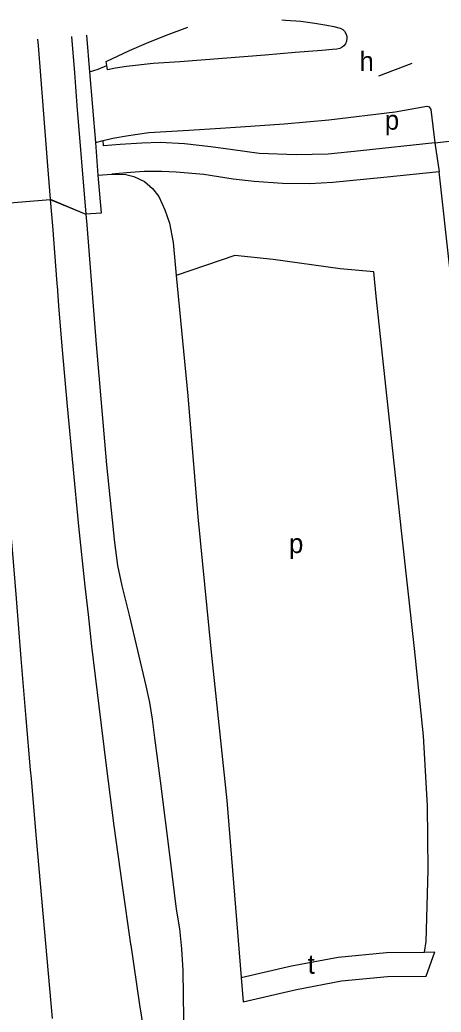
# Model space of a CAD drawing. Extents: x 157646 to 159241, y 379213 to 381217.
# Drawn here: x 157938.7 to 158026.1, y 380686.9 to 380892.6 of the extents above; entities that cross this region are included whole.
import ezdxf

# ---------------------------------------------------------------- set-up
doc = ezdxf.new("R2010")
doc.units = 0
for name, color, linetype in [('BLT_Basislijn', 7, 'Continuous'), ('BLT_Centroide', 7, 'Continuous'), ('BLT_Vlakafsluiter', 7, 'Continuous')]:
    doc.layers.add(name, color=color, linetype=linetype)

msp = doc.modelspace()

# ---------------------------------------------------------------- linework, layer by layer
at = {"layer": 'BLT_Basislijn'}
for p, q in [((157952.53, 380889.43), (157953.11, 380881.88)), ((157953.11, 380881.88), (157954.35, 380867.22)), ((158013.16, 380881.03), (158020.02, 380883.66)), ((157954.35, 380867.22), (157954.89, 380860.42)), ((158024.73, 380867.15), (158024.73, 380867.1)), ((158024.73, 380867.1), (158025.62, 380861.15)), ((157954.89, 380860.42), (157957.77, 380860.62)), ((157931.44, 380854.27), (157945, 380855.41)), ((158022.95, 380694.36), (158024.76, 380699.38)), ((157984.57, 380694.09), (157985.02, 380689.06))]:
    msp.add_line(p, q, dxfattribs=at)
for points in [[(157992.99, 380892.63), (157993.75, 380892.58), (157996.98, 380892.37), (157999.85, 380891.95), (158002.36, 380891.55), (158003.77, 380891.24), (158005.13, 380890.93)], [(157956.74, 380883.18), (157956.62, 380883.96), (157961.45, 380886.29), (157964.96, 380887.8), (157968.89, 380889.37), (157973.5, 380891.09)], [(158005.13, 380890.93), (158005.69, 380890.64), (158006, 380890.28), (158006.3, 380889.8), (158006.47, 380889.28), (158006.5, 380888.82), (158006.43, 380888.19), (158006.24, 380887.69), (158005.9, 380887.25), (158005.53, 380886.95), (158005.01, 380886.66), (158004.39, 380886.52), (158003.53, 380886.46), (158001.34, 380886.27), (157995.76, 380885.89), (157989.54, 380885.33), (157971.89, 380883.94), (157966.36, 380883.61), (157960.8, 380882.94), (157958.5, 380882.58), (157956.85, 380882.3), (157956.74, 380883.18)], [(157942.37, 380888.63), (157942.47, 380887.3), (157942.97, 380881.08)], [(157949.42, 380889.19), (157950.01, 380881.64)], [(157953.11, 380881.88), (157954.93, 380882.42), (157956.74, 380883.18)], [(157942.97, 380881.08), (157943.46, 380874.84), (157944.45, 380862.38), (157944.99, 380855.47)], [(157950.01, 380881.64), (157950.53, 380874.88), (157952.38, 380852.37)], [(157955.99, 380867.6), (157957.97, 380868.07), (157961.25, 380868.65), (157965.47, 380869.29), (157973.75, 380869.75), (157980.29, 380870.15), (157986.55, 380870.57), (157993.48, 380871.09), (158002.78, 380871.88), (158016.52, 380873.55), (158023.06, 380874.7), (158023.56, 380874.59), (158023.91, 380874.04), (158024.73, 380867.15)], [(157954.35, 380867.22), (157955.99, 380867.6)], [(158024.73, 380867.15), (158009.31, 380865.45), (158002.62, 380864.8), (157995.96, 380864.62), (157988.32, 380864.93), (157982.88, 380865.66), (157978.29, 380866.3), (157972.8, 380866.94), (157967.78, 380867.21), (157964.01, 380867.09), (157959.51, 380866.79), (157956.04, 380866.51), (157955.99, 380867.6)], [(157954.89, 380860.42), (157955.55, 380852.58), (157952.38, 380852.32)], [(158025.62, 380861.15), (158014.17, 380859.91), (158003.57, 380858.91), (157998.74, 380858.66), (157993.12, 380858.69), (157987.28, 380859.09), (157982.92, 380859.63), (157976.84, 380860.6), (157971.1, 380861.03), (157968.08, 380861.19), (157964.45, 380861.18), (157961.61, 380860.97), (157957.77, 380860.62)], [(157957.77, 380860.62), (157960.67, 380860.56), (157962.36, 380860.16), (157964.51, 380859.09), (157966.23, 380857.68), (157967.5, 380855.99), (157968.78, 380853.22), (157969.72, 380850.49), (157970.45, 380846.47), (157971.08, 380839.65)], [(158045.23, 380685.9), (158045.55, 380693.84), (158045.39, 380702.14), (158044.61, 380715.8), (158043.71, 380724.16), (158042.44, 380732.51), (158040.38, 380743.25), (158038.2, 380752.94), (158036.88, 380760.03), (158035.82, 380767.7), (158032.55, 380798.05), (158028.93, 380831.12), (158025.98, 380858.02), (158025.62, 380861.15)], [(157944.99, 380855.47), (157945, 380855.41)], [(157945, 380855.41), (157945.43, 380849.91), (157946.37, 380838), (157946.39, 380837.79), (157946.42, 380837.45), (157946.74, 380833.33), (157947.42, 380824.99), (157948.5, 380812.54), (157949.65, 380800.09), (157950.88, 380787.64), (157952.19, 380775.21), (157952.83, 380769.37), (157953.58, 380762.78), (157955.05, 380750.37), (157956.59, 380737.96), (157958.21, 380725.56), (157959.91, 380713.18), (157961.65, 380701.01), (157961.68, 380700.8), (157963.53, 380688.44), (157965.14, 380678.13)], [(157931.44, 380854.27), (157931.99, 380847.37), (157932.98, 380834.91), (157933.26, 380831.36), (157933.96, 380822.45), (157934.95, 380809.99), (157935.93, 380797.53), (157936.81, 380786.35), (157936.92, 380785.07), (157937.09, 380782.85), (157937.91, 380772.63), (157938.93, 380760.19), (157939.96, 380747.76), (157940.86, 380737.13), (157941.01, 380735.32), (157941.09, 380734.43), (157942.09, 380722.89), (157943.18, 380710.46), (157944.29, 380698.04), (157945.42, 380685.61)], [(157952.38, 380852.37), (157952.38, 380852.32)], [(157952.38, 380852.32), (157952.56, 380850.15), (157954.53, 380825.35), (157956.67, 380800.34), (157958.35, 380784.24), (157958.96, 380779.49), (157959.83, 380775.32), (157961.34, 380769.23), (157964.83, 380754.53), (157965.59, 380751.11), (157966.1, 380747.61), (157966.63, 380743.8), (157967.81, 380734.85), (157969.81, 380718.96), (157971.14, 380708.26), (157971.78, 380704.18), (157972.21, 380700.04), (157972.49, 380695.53), (157972.56, 380690.36), (157972.68, 380681.01)], [(158022.63, 380699.36), (158022.97, 380701.57), (158023.34, 380716.38), (158023.25, 380729.7), (158022.41, 380744.22), (158020.55, 380762.29), (158017.85, 380786.69), (158014.87, 380814.12), (158012.59, 380835.31), (158012.1, 380840.36), (158005.09, 380841.01), (157991.24, 380842.97), (157983.26, 380843.78)], [(157971.08, 380839.65), (157973.54, 380814.66), (157975.59, 380789.61), (157978.34, 380761.55), (157981.6, 380730.75), (157984.57, 380694.09)], [(157984.57, 380694.09), (157995.04, 380696.52), (158004.7, 380698.32), (158014.69, 380699.27), (158022.63, 380699.36)], [(158022.63, 380699.36), (158024.76, 380699.38)], [(157985.02, 380689.06), (157996.06, 380691.62), (158005.39, 380693.36), (158014.95, 380694.27), (158022.95, 380694.36)]]:
    msp.add_lwpolyline(points, dxfattribs=at)
at = {"layer": 'BLT_Vlakafsluiter'}
for p, q in [((158024.73, 380867.15), (158041.04, 380869.07)), ((158024.73, 380867.1), (158041.01, 380869.02)), ((157944.99, 380855.47), (157952.38, 380852.37)), ((157945, 380855.41), (157952.38, 380852.32)), ((157983.26, 380843.78), (157971.08, 380839.65))]:
    msp.add_line(p, q, dxfattribs=at)

# ---------------------------------------------------------------- texts
at = {"layer": 'BLT_Centroide'}
for s, p in [('h', (158009.11, 380882.04)), ('p', (158014.37, 380869.86)), ('p', (157994.5, 380782.08)), ('t', (157998.37, 380694.87))]:
    msp.add_text(s, height=4, dxfattribs=at).set_placement(p)

doc.saveas('drawing.dxf')
